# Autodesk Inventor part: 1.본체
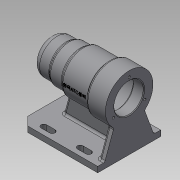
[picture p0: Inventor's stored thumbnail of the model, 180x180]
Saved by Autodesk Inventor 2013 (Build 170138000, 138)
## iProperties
Created: 2017-09
Part Number: 1.본체
Material: 일반
Document SubType Name: Modeling
Designer: Administrator
Density: 1 g/cm^3
Author: Administrator
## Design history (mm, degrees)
sketch "스케치1"
  geometry: L1 (56, -45)-(-44, -45); L2 (-56, -33)-(-56, 33); L3 (-44, 45)-(56, 45); L4 (56, 45)-(56, -45); L5 (56, -45)-(-56, 45); L6 (-56, -45)-(56, 45); L7 (-56, 33)-(-44, 45); L8 (-44, -45)-(-56, -33); 1 further point
  constraints: 16 end point, 4 point on line, 2 midpoint, 2 parallel, 1 horizontal, 1 perpendicular
  dimensions: "d0" = 112 distance of L5.end L3.end; "d2" = 90 distance of L3.end L1.start; "d3" = 12 distance of L2.end L5.end; "d4" = 12 distance of L3.start L5.end (= d3); "d5" = 12 distance of L1.end L6.start (= d3); "d6" = 12 distance of L2.start L6.start (= d5)
extrude "돌출1" new body sketch "스케치1" distance "d7" = 8; taper "d8" = 0 deg
sketch "스케치2"
  geometry: L1 (-56, 70)-(56, 70); L2 (44, 0)-(-56, 0) reference; L3 (56, 70)-(56, 95); L4 (56, 95)-(31, 95); L5 (31, 95)-(31, 97); L6 (31, 97)-(11, 97); L7 (11, 97)-(11, 100); L8 (11, 100)-(-28, 100); L9 (-28, 100)-(-28, 104); L10 (-28, 104)-(-56, 104); L11 (-56, 104)-(-56, 70); L12 (-56, 0)-(-56, 8) reference; L13 (56, 0)-(44, 0) reference; 2 further points
  constraints: 20 end point, 7 parallel, 2 perpendicular, 1 horizontal, 1 midpoint, 1 point on line
  dimensions: "d9" = 70 distance from line of L1.start L2; "d10" = 112 distance of L1.start L1.end; "d11" = 25 distance of L3.end L4.end; "d12" = 45 distance between parallel lines of L7 L3; "d13" = 84 distance between parallel lines of L9 L3; "d14" = 50 diameter of L4 L1; "d15" = 54 diameter of L6 L1; "d16" = 60 diameter of L8 L1; "d17" = 68 diameter of L10 L1
revolve "회전1" sketch "스케치2" stored, may be unused: angle "d18" = 90 deg
sketch "스케치3"
  geometry: L1 (-56, 36)-(-56, 104) reference; L2 (56, 45)-(56, 95) reference; L3 (56, 70)-(-56, 70); L4 (-56, 91)-(-41, 91); L5 (-41, 91)-(-41, 91); L6 (-38, 94)-(10, 94); L7 (13, 91)-(13, 91); L8 (13, 91)-(24.7, 91); L9 (25, 90.7)-(25, 87.5); L10 (25, 87.5)-(42.7, 87.5); L11 (43, 87.2)-(43, 86); L12 (43, 86)-(46.7, 86); L13 (47, 85.7)-(47, 80.5); L14 (47, 80.5)-(47, 80.5); L15 (50, 77.5)-(50, 70); A1 r 3 centre (47, 77.5) between (50, 77.5) and (47, 80.5); A2 r 0.3 centre (46.7, 85.7) between (47, 85.7) and (46.7, 86); A3 r 0.3 centre (42.7, 87.2) between (43, 87.2) and (42.7, 87.5); A4 r 0.3 centre (24.7, 90.7) between (25, 90.7) and (24.7, 91); A5 r 3 centre (10, 91) between (13, 91) and (10, 94); A6 r 3 centre (-38, 91) between (-38, 94) and (-41, 91); 7 further points
  constraints: 26 end point, 14 point on line, 12 point on circle, 12 tangent, 10 parallel, 6 centre point, 2 collinear, 2 equal radius, 2 midpoint, 1 perpendicular
  dimensions: "d19" = 42 diameter of L4 L3; "d21" = 48 diameter of L6 L3; "d22" = 54 distance of point (-41, 94) point (13, 94); "d23" = 15 distance of L4.start L4.end; "d24" = 12 distance of L7.end point (25, 91); "d25" = 18 distance of L9.end point (43, 87.5); "d26" = 4 distance of L11.end point (47, 86); "d27" = 3 distance of L13.end point (50, 80.5); "d28" = 21 diameter of L14 L3; "d29" = 32 diameter of L12 L3; "d30" = 35 diameter of L10 L3; "d31" = 3 radius of A1; "d32" = 0.3 radius of A2; "d33" = 3 radius of A5; "d34" = 3 radius of A6
revolve "회전2" sketch "스케치3" stored, may be unused: angle "d35" = 90 deg
chamfer "모따기1" distance "d36" = 1; stored, may be unused: second distance "d37" = 2, angle "d38" = 45 deg
sketch "스케치5"
  geometry: L1 (0, 90)-(-8, 90) reference; L2 (-8, 0)-(-8, 90) reference; L3 (0, 0)-(-8, 0) reference; L4 (-43.992, 23.1)-(-8, 10); L5 (-43.992, 66.9)-(-8, 80); A1 r 34 centre (-70, 45) between (-43.992, 23.1) and (-43.992, 66.9) reference; 1 further point
  constraints: 4 end point, 2 point on circle, 2 point on line
  dimensions: "d41" = 10 distance from line of L4.end L3; "d42" = 10 distance from line of L5.end L1; "d43" = 110 deg angle of L4 L2; "d44" = 110 deg angle of L5 L2
extrude "돌출2" join sketch "스케치5" distance "d45" = 8; taper "d46" = 0 deg
sketch "스케치6"
  geometry: L1 (44, 8)-(-56, 8) reference; L2 (56, 0)-(56, 8) reference; L3 (56, 8)-(44, 8) reference; L4 (-48, 8)-(-48, 43.992) reference; L5 (-48, 36)-(-28, 36) reference; L6 (-28, 40)-(11, 40) reference; L7 (-28, 36)-(-28, 104) reference; L8 (11, 40)-(11, 100) reference; L9 (11, 43)-(31, 43) reference; L10 (31, 45)-(31, 95) reference; L11 (24.622, 43)-(34, 8); 1 further point
  constraints: 2 end point, 2 point on line
  dimensions: "d47" = 105 deg angle of L11 L1; "d48" = 22 distance from line of L2 L11.end
feature "리브1" sketch "스케치6" dims "d49" = 1, "d50" = 8, "d51" = 0, "d52" = 0, "d53" = 1, "d54" = 1
sketch "스케치7"
  geometry: L1 (56, -45)-(56, -35) reference; L2 (48, -35)-(48, -4) reference; L3 (-20, -34)-(20, -34); L4 (20, -30)-(32, -30); L5 (32, -38)-(20, -38); L6 (-20, -38)-(-32, -38); L7 (-32, -30)-(-20, -30); A1 r 4 centre (20, -34) between (20, -30) and (20, -38); A2 r 4 centre (32, -34) between (32, -30) and (32, -38); A3 r 4 centre (-32, -34) between (-32, -30) and (-32, -38); A4 r 4 centre (-20, -34) between (-20, -30) and (-20, -38); 1 further point
  constraints: 10 end point, 8 point on circle, 5 tangent, 4 centre point, 3 parallel, 2 coincident, 2 horizontal alignment, 1 perpendicular
  dimensions: "d55" = 40 distance of L3.start L3.end; "d57" = 34 distance from line of point (0, 0) L3; "d59" = 12 distance of A2.centre A1.centre; "d60" = 8 diameter of A1; "d61" = 8 diameter of A2; "d62" = 12 distance of A4.centre A3.centre; "d63" = 8 diameter of A3; "d64" = 8 diameter of A4; "d67" = 24 distance from line of A2.centre L1
extrude "돌출3" cut sketch "스케치7" stored distance "d65" = 8; taper "d66" = 0 deg
sketch "스케치8"
  geometry: A1 r 34 centre (-70, 45) between (-43.992, 66.9) and (-43.992, 23.1) reference; 2 further points
  constraints: 1 horizontal alignment
  dimensions: "d68" = 26 distance of point (-96, 45) A1.centre
hole "구멍1" sketch "스케치8" at (-96, 45) diameter "d69" = 3.242; stored, may be unused: countersink angle "d73" = 90 deg, drill point angle "d75" = 118 deg; dims "d70" = 8, "d71" = 4, "d72" = 2, "d74" = 11
fillet "모깎기1" dims "d79" = 9
fillet "모깎기2" dims "d80" = 3
fillet "모깎기3" dims "d81" = 3
fillet "모깎기4" dims "d82" = 3
fillet "모깎기6" dims "d84" = 3
fillet "모깎기7" dims "d85" = 2
fillet "모깎기8" dims "d86" = 3
fillet "모깎기9" dims "d87" = 3
fillet "모깎기10" dims "d88" = 3
node "작업 평면1"
sketch "스케치9"
  geometry: L1 (56, 104)-(56, 45.289) reference; L2 (56, 0)-(-44, 0) reference; 3 further points
  constraints: 1 other
  dimensions: "d90" = 48 distance from line of point (8, 70) L1; "d91" = 70 distance from line of point (8, 70) L2
feature "엠보싱1" sketch "스케치9" dims "d0" = 112, "d2" = 90, "d3" = 12, "d4" = 12 (= d3), "d5" = 12 (= d3), "d6" = 12 (= d5), "d92" = 0.5, "d93" = 0
node "솔리드1"
mirror "대칭1"
pattern_circular "원형 패턴1" dims angle "d77" = 360 deg
other parameters: "d89" = -54
